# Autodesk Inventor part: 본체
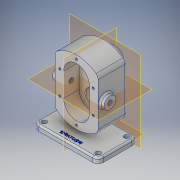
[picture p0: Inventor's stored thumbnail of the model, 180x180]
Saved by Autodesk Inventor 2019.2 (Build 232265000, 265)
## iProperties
Created: 2019-03
Part Number: 본체
Material: 알루미늄 6061
Document SubType Name: Modeling
Designer: User
Density: 2.7 g/cm^3
Appearance: 알루미늄 - 평지
Mass: 1185.36 g
Surface Area: 720.534 cm^2
Volume: 439.024 cm^3
Author: User
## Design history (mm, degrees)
sketch "스케치1"
  geometry: L1 (0, 84)-(0, -84) reference; L2 (-56, 0)-(56, 0) reference; L3 (-40, 44.721)-(-40, -44.721); L4 (40, -44.721)-(40, 44.721); A1 r 60 centre (0, 0) between (-40, -44.721) and (40, -44.721); A2 r 60 centre (0, 0) between (40, 44.721) and (-40, 44.721); 1 further point
  constraints: 4 end point, 4 point on circle, 2 centre point, 2 vertical, 1 coincident
  dimensions: "d1" = 80 distance between parallel lines of L4 L3; "d2" = 40 distance between parallel lines of L4 L1; "d3" = 60 radius of A2; "d4" = 60 radius of A1
extrude "돌출1" new body sketch "스케치1" distance "d5" = 53; taper "d6" = 0 deg
sketch "스케치2"
  geometry: L1 (0, 84)-(0, -84) reference; C1 r 19 at (0, 22); 1 further point
  constraints: 1 centre point, 1 point on line
  dimensions: "d7" = 38 diameter of C1; "d8" = 22 distance of point (0, 0) C1.centre
extrude "돌출2" join sketch "스케치2" distance "d9" = 70; taper "d10" = 0 deg
sketch "스케치3"
  geometry: L1 (44.721, 53)-(-44.721, 53) reference; L2 (0, 67)-(0, -31) reference; C1 r 11 at (0, 39); 1 further point
  constraints: 1 centre point, 1 point on line
  dimensions: "d11" = 22 diameter of C1; "d12" = 14 distance from line of L1 C1.centre
extrude "돌출3" join sketch "스케치3" stored distance "d13" = 96; taper "d14" = 0 deg
node "작업 평면1"
sketch "스케치4"
  geometry: L1 (60, 0)-(-60, 0); L2 (-60, 0)-(-60, 73); L3 (-60, 73)-(60, 73); L4 (60, 73)-(60, 0); L5 (0, -35)-(0, 91) reference; L6 (-84, 0)-(84, 0) reference; 1 further point
  constraints: 8 end point, 2 parallel, 1 collinear, 1 horizontal, 1 perpendicular
  dimensions: "d16" = 73 distance of L3.end L1.start; "d17" = 120 distance of L2.end L3.end; "d18" = 60 distance between parallel lines of L5 L4
extrude "돌출4" join sketch "스케치4" distance "d19" = 10; taper "d20" = 0 deg
sketch "스케치5"
  geometry: L1 (-45.169, 43)-(-68, 43); L2 (-68, 43)-(-68, 0); L3 (-68, 0)-(-45.169, 0); L4 (-45.169, 0)-(-45.169, 43); L5 (-68, 0)-(-68, 73) reference; L6 (-78, 0)-(-68, 0) reference; 1 further point
  constraints: 8 end point, 2 collinear, 2 parallel, 1 horizontal, 1 perpendicular
  dimensions: "d21" = 43 distance of L1.end L2.end; "d22" = 22.83133 distance of L1.start L1.end
extrude "돌출5" join sketch "스케치5" stored distance "d23" = 12; taper "d24" = 0 deg
sketch "스케치6"
  geometry: L1 (0, -22)-(0, 22); L2 (24, -22)-(24, 22); L3 (-24, 22)-(-24, -22); L4 (-84, 0)-(84, 0) reference; L5 (0, -105.6)-(0, 87.6) reference; A1 r 24 centre (0, -22) between (-24, -22) and (24, -22); A2 r 24 centre (0, 22) between (24, 22) and (-24, 22); 2 further points
  constraints: 8 end point, 4 point on circle, 4 tangent, 2 centre point, 1 collinear, 1 midpoint, 1 parallel, 1 vertical, 1 other
  dimensions: "d25" = 24 radius of A2; "d26" = 44 distance of L2.start L2.end
extrude "돌출6" cut sketch "스케치6" distance "d27" = 29; taper "d28" = 0 deg
sketch "스케치7"
  geometry: A1 r 24 centre (0, 22) between (24, 22) and (-24, 22) reference; 2 further points
  constraints: 1 coincident
hole "구멍1" sketch "스케치7" at (0, 22) diameter "d29" = 17; stored, may be unused: countersink angle "d33" = 90 deg, drill point angle "d35" = 118 deg; dims "d30" = 9, "d31" = 25, "d32" = 15, "d34" = 50
sketch "스케치8"
  geometry: A1 r 24 centre (0, -22) between (-24, -22) and (24, -22) reference; 2 further points
  constraints: 1 coincident
hole "구멍2" sketch "스케치8" at (0, -22) diameter "d36" = 25; stored, may be unused: countersink angle "d40" = 90 deg, drill point angle "d42" = 0 deg; dims "d37" = 9, "d38" = 25, "d39" = 17, "d41" = 15
sketch "스케치9"
  geometry: C1 r 19 at (0, 0) reference; 2 further points
  constraints: 1 coincident
hole "구멍3" sketch "스케치9" at (0, 0) diameter "d43" = 28; stored, may be unused: countersink angle "d47" = 90 deg, drill point angle "d49" = 0 deg; dims "d44" = 9, "d45" = 25, "d46" = 17, "d48" = 7.3
sketch "스케치10"
  geometry: C1 r 11 at (0, 0) reference; 2 further points
  constraints: 1 coincident
hole "구멍4" sketch "스케치10" at (0, 0) diameter "d50" = 8.376; stored, may be unused: countersink angle "d54" = 90 deg, drill point angle "d56" = 0 deg; dims "d51" = 50, "d52" = 25, "d53" = 17, "d55" = 50
sketch "스케치11"
  geometry: C1 r 11 at (0, 0) reference; 2 further points
  constraints: 1 coincident
hole "구멍5" sketch "스케치11" at (0, 0) diameter "d57" = 8.376; stored, may be unused: countersink angle "d61" = 90 deg, drill point angle "d63" = 0 deg; dims "d58" = 50, "d59" = 25, "d60" = 17, "d62" = 50
sketch "스케치12"
  geometry: L1 (-24, -22)-(-24, 22) reference; L2 (24, 22)-(24, -22) reference; L3 (-31, 22)-(-31, -22); L4 (31, -22)-(31, 22); A1 r 24 centre (0, 22) between (24, 22) and (-24, 22) reference; A2 r 24 centre (0, -22) between (-24, -22) and (24, -22) reference; A3 r 31 centre (0, -22) between (-31, -22) and (31, -22); A4 r 31 centre (0, 22) between (31, 22) and (-31, 22); 1 further point
  constraints: 4 end point, 4 point on circle, 2 centre point, 3 other
  dimensions: "d64" = 7 radial gap between concentric circles of A1 A4
hole "구멍6" sketch "스케치12" at (-31, -22), (-31, 22), (31, 22), (31, -22) diameter "d65" = 4.134; stored, may be unused: countersink angle "d69" = 90 deg, drill point angle "d71" = 118 deg; dims "d66" = 10, "d67" = 25, "d68" = 17, "d70" = 12
sketch "스케치13"
  geometry: L1 (0, 0)-(0, 53)
  constraints: 2 end point, 1 vertical
  dimensions: "d72" = 53 distance of L1.start L1.end
hole "구멍7" sketch "스케치13" at (0, 53) diameter "d73" = 4.134; stored, may be unused: countersink angle "d77" = 90 deg, drill point angle "d79" = 118 deg; dims "d74" = 10, "d75" = 25, "d76" = 17, "d78" = 12
chamfer "모따기1" distance "d80" = 1; stored, may be unused: second distance "d81" = 2, angle "d82" = 45 deg
fillet "모깎기1" dims "d83" = 10
sketch "스케치14"
  geometry: A1 r 10 centre (-50, -63) between (-60, -63) and (-50, -73) reference; A2 r 10 centre (-50, -10) between (-50, 0) and (-60, -10) reference; A3 r 10 centre (50, -63) between (50, -73) and (60, -63) reference; A4 r 10 centre (50, -10) between (60, -10) and (50, 0) reference; 5 further points
  constraints: 4 coincident
hole "구멍8" sketch "스케치14" at (-50, -63), (-50, -10), (50, -63), (50, -10) diameter "d84" = 9; stored, may be unused: countersink angle "d88" = 90 deg, drill point angle "d90" = 118 deg; dims "d85" = 10, "d86" = 25, "d87" = 17, "d89" = 12
fillet "모깎기3" dims "d92" = 10
fillet "모깎기4" dims "d93" = 3
fillet "모깎기5" dims "d94" = 3
fillet "모깎기6" dims "d95" = 3
fillet "모깎기7" dims "d96" = 3
fillet "모깎기8" dims "d97" = 0.5
chamfer "모따기2" distance "d98" = 0.7; stored, may be unused: second distance "d99" = 2, angle "d100" = 30 deg
sketch "스케치15"
  geometry: L1 (-60, -10)-(-60, -63) reference; L2 (-50, -73)-(50, -73) reference; 2 further points
  constraints: 1 other
  dimensions: "d101" = 60 distance from line of L1 point (0, -63); "d102" = 10 distance from line of L2 point (0, -63)
feature "엠보싱1" sketch "스케치15" dims "d103" = 0.5, "d104" = 0
node "솔리드1"
mirror "미러1"
other parameters: "d15" = -78
